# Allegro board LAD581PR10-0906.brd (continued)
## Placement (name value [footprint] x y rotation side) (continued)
PC720  100P_0402_50V8J  [C_0402]  60.01 39.45 270 top
PC721  0.1U_0402_25V6  [C_0402]  52.02 35.38 90 top
PC722  1000P_0402_50V7K  [C_0402]  47.37 50 0 bottom
PC723  1000P_0402_50V7K  [C_0402]  47.39 43.07 180 top
PC724  0.1U_0402_25V6  [C_0402]  89.13 72.17 180 top
PC725  0.022U_0603_25V7K  [C_0603]  65.04 22.95 180 top
PC726  1000P_0402_50V7K  [C_0402]  55.57 28.67 90 top
PC727  1U_0402_25V6K  [C_0402]  56.46 28.67 90 top
PC800  10U_0805_25V6K~D  [C_0805]  162.36 149.69 0 bottom
PC801  0.01U_0402_16V7K  [C_0402]  161.76 155.79 180 bottom
PC802  680P_0402_50V7K  [C_0402]  162.26 150 90 top
PC803  2.2U_0402_16V6K  [C_0402]  168.4 155.28 0 bottom
PC804  22U_0603_6.3V6M  [C_0603]  173.56 153.12 90 bottom
PC805  22U_0603_6.3V6M  [C_0603]  174.83 153.12 90 bottom
PC806  680P_0402_50V7K  [C_0402]  238.77 148.37 270 bottom
PC807  2.2U_0402_16V6K  [C_0402]  93.74 103.8 270 bottom
PC808  0.1U_0603_25V7K  [C_0603]  166.57 148.7 90 bottom
PC809  330P_0402_50V7K  [C_0402]  165.43 158.41 270 bottom
PC810  10U_0603_6.3V6M  [C_0603]  240.55 148.23 0 bottom
PC811  0.1U_0402_16V7K  [C_0402]  238.9 154.06 90 bottom
PC812  22U_0603_6.3V6M  [C_0603]  234.91 148.05 180 bottom
PC813  22U_0603_6.3V6M  [C_0603]  234.91 149.31 180 bottom
PC814  1U_0603_6.3V6M  [C_0603]  240.55 149.5 0 bottom
PC815  22U_0603_6.3V6M  [C_0603]  235.89 148.05 0 bottom
PC816  22P_0603_50V8  [C_0603]  243.03 154.71 270 bottom
PC817  1U_0603_6.3V6M  [C_0603]  166.64 156.55 0 bottom
PC818  22U_0603_6.3V6M  [C_0603]  168.23 153.57 90 top
PC819  22U_0603_6.3V6M  [C_0603]  169.42 153.57 90 top
PC820  330P_0402_50V7K  [C_0402]  92.55 113.82 180 bottom
PC1000  220U_D7_2VM_R6M  [C_EEFSS0D221R]  134.04 117.65 0 bottom
PC1001  220U 2.5V Y D2 ESR9M H1.9 SX  [C_D2]  131.47 119.64 0 top
PC1002  220U 2.5V Y D2 ESR9M H1.9 SX  [C_D2]  141.65 119.63 0 top
PC1003  47U_0805_6.3V6M  [C_0805]  148.54 118.18 270 bottom
PC1004  47U_0805_6.3V6M  [C_0805]  146.63 118.18 270 bottom
PC1005  47U_0805_6.3V6M  [C_0805]  135.25 98.59 0 top
PC1006  47U_0805_6.3V6M  [C_0805]  150.44 118.18 270 bottom
PC1007  220U 2.5V Y D2 ESR9M H1.9 SX  [C_D2]  120.45 119.59 0 top
PC1008  220U_D7_2VM_R6M  [C_EEFSS0D221R]  120.25 117.69 180 bottom
PC1009  220U_D7_2VM_R6M  [C_EEFSS0D221R]  110.02 117.33 180 bottom
PC1010  220U_D7_2VM_R6M  [C_EEFSS0D221R]  124.32 117.75 0 bottom
PC1011  47U_0805_6.3V6M  [C_0805]  110.25 120.48 90 top
PC1012  47U_0805_6.3V6M  [C_0805]  117.36 120.48 90 top
PC1013  47U_0805_6.3V6M  [C_0805]  112.03 120.48 90 top
PC1014  47U_0805_6.3V6M  [C_0805]  120.56 122.96 180 top
PC1015  47U_0805_6.3V6M  [C_0805]  113.8 120.48 90 top
PC1016  47U_0805_6.3V6M  [C_0805]  115.58 120.48 90 top
PC1017  220U_D2_2.5VY_R9M  [C_D2]  151.75 119.53 0 top
PC1018  47U_0805_6.3V6M  [C_0805]  135.25 100.3 0 top
PC1019  10U_0402_6.3V6M  [C_0402]  136.03 104.56 0 top
PC1020  22U_0603_6.3V6M  [C_0603]  127.34 99.16 0 top
PC1021  22U_0603_6.3V6M  [C_0603]  127.34 97.96 0 top
PC1022  22U_0603_6.3V6M  [C_0603]  126.39 99.16 180 top
PC1023  22U_0603_6.3V6M  [C_0603]  126.39 97.96 180 top
PC1024  22U_0603_6.3V6M  [C_0603]  131.09 97.96 180 top
PC1025  22U_0603_6.3V6M  [C_0603]  131.09 99.16 180 top
PC1026  22U_0603_6.3V6M  [C_0603]  132.04 99.16 0 top
PC1027  22U_0603_6.3V6M  [C_0603]  132.04 97.96 0 top
PC1028  22U_0603_6.3V6M  [C_0603]  111.21 99.54 0 top
PC1029  22U_0603_6.3V6M  [C_0603]  108.86 99.54 0 top
PC1030  22U_0603_6.3V6M  [C_0603]  115.91 99.54 0 top
PC1031  22U_0603_6.3V6M  [C_0603]  113.56 99.54 0 top
PC1032  22U_0603_6.3V6M  [C_0603]  118.26 99.54 0 top
PC1033  22U_0603_6.3V6M  [C_0603]  120.99 99.61 0 top
PC1034  22U_0603_6.3V6M  [C_0603]  121 100.82 0 top
PC1035  22U_0603_6.3V6M  [C_0603]  121 102.16 0 top
PC1036  10U_0402_6.3V6M  [C_0402]  135.16 102.53 180 top
PC1037  10U_0402_6.3V6M  [C_0402]  136.03 103.67 0 top
PC1038  10U_0402_6.3V6M  [C_0402]  136.03 105.96 0 top
PC1039  10U_0402_6.3V6M  [C_0402]  135.16 103.42 180 top
PC1040  10U_0402_6.3V6M  [C_0402]  135.16 101.64 180 top
PC1041  10U_0402_6.3V6M  [C_0402]  136.03 101.64 0 top
PC1042  1U_0201_6.3V6M  [C_0201]  135.32 105.19 180 top
PC1043  1U_0201_6.3V6M  [C_0201]  135.32 106.34 180 top
PC1044  1U_0201_6.3V6M  [C_0201]  135.32 105.77 180 top
PC1045  10U_0402_6.3V6M  [C_0402]  125.96 102.53 180 top
PC1046  10U_0402_6.3V6M  [C_0402]  126.82 101.26 0 top
PC1047  10U_0402_6.3V6M  [C_0402]  125.96 103.42 180 top
PC1048  10U_0402_6.3V6M  [C_0402]  125.96 101.26 180 top
PC1049  10U_0402_6.3V6M  [C_0402]  126.82 103.42 0 top
PC1050  10U_0402_6.3V6M  [C_0402]  129.39 96.69 180 top
PC1051  10U_0402_6.3V6M  [C_0402]  126.82 102.53 0 top
PC1052  10U_0402_6.3V6M  [C_0402]  126.69 96.69 0 top
PC1053  10U_0402_6.3V6M  [C_0402]  129.39 95.8 180 top
PC1054  10U_0402_6.3V6M  [C_0402]  130.57 101.26 0 top
PC1055  10U_0402_6.3V6M  [C_0402]  126.69 95.8 0 top
PC1056  10U_0402_6.3V6M  [C_0402]  129.7 101.26 180 top
PC1057  10U_0402_6.3V6M  [C_0402]  129.7 103.42 180 top
PC1058  10U_0402_6.3V6M  [C_0402]  129.7 102.53 180 top
PC1059  10U_0402_6.3V6M  [C_0402]  123.56 104.22 180 top
PC1060  10U_0402_6.3V6M  [C_0402]  113.6 97.22 0 top
PC1061  10U_0402_6.3V6M  [C_0402]  109.04 96.3 0 top
PC1062  10U_0402_6.3V6M  [C_0402]  111.32 98.1 0 top
PC1063  10U_0402_6.3V6M  [C_0402]  111.33 102.89 0 top
PC1064  10U_0402_6.3V6M  [C_0402]  118.51 100.62 0 top
PC1065  10U_0402_6.3V6M  [C_0402]  116.04 100.61 0 top
PC1066  10U_0402_6.3V6M  [C_0402]  109.08 101.98 0 top
PC1067  10U_0402_6.3V6M  [C_0402]  113.62 102.89 0 top
PC1068  10U_0402_6.3V6M  [C_0402]  109.04 97.2 0 top
PC1069  10U_0402_6.3V6M  [C_0402]  113.6 96.31 0 top
PC1070  10U_0402_6.3V6M  [C_0402]  111.34 102.02 0 top
PC1071  10U_0402_6.3V6M  [C_0402]  130.57 103.42 0 top
PC1072  10U_0402_6.3V6M  [C_0402]  130.25 95.8 0 top
PC1073  10U_0402_6.3V6M  [C_0402]  130.57 102.53 0 top
PC1074  10U_0402_6.3V6M  [C_0402]  130.25 96.69 0 top
PC1075  10U_0402_6.3V6M  [C_0402]  133.26 103.42 180 top
PC1076  10U_0402_6.3V6M  [C_0402]  133.26 101.26 180 top
PC1077  10U_0402_6.3V6M  [C_0402]  132.94 95.8 180 top
PC1078  10U_0402_6.3V6M  [C_0402]  133.26 102.53 180 top
PC1079  10U_0402_6.3V6M  [C_0402]  133.81 95.8 0 top
PC1080  10U_0402_6.3V6M  [C_0402]  133.81 96.69 0 top
PC1081  10U_0402_6.3V6M  [C_0402]  136.5 96.69 180 top
PC1082  10U_0402_6.3V6M  [C_0402]  132.94 96.69 180 top
PC1083  10U_0402_6.3V6M  [C_0402]  125.83 96.69 180 top
PC1084  10U_0402_6.3V6M  [C_0402]  125.83 95.8 180 top
PC1085  10U_0402_6.3V6M  [C_0402]  118.26 96.29 0 top
PC1086  10U_0402_6.3V6M  [C_0402]  118.27 98.09 0 top
PC1087  10U_0402_6.3V6M  [C_0402]  115.93 96.29 0 top
PC1088  10U_0402_6.3V6M  [C_0402]  118.45 102.94 0 top
PC1089  10U_0402_6.3V6M  [C_0402]  115.92 98.09 0 top
PC1090  10U_0402_6.3V6M  [C_0402]  120.53 96.3 0 top
PC1091  10U_0402_6.3V6M  [C_0402]  123.53 103.35 180 top
PC1092  10U_0402_6.3V6M  [C_0402]  115.92 97.19 0 top
PC1093  10U_0402_6.3V6M  [C_0402]  120.54 97.18 0 top
PC1094  10U_0402_6.3V6M  [C_0402]  111.31 96.31 0 top
PC1095  10U_0402_6.3V6M  [C_0402]  115.97 102.9 0 top
PC1096  10U_0402_6.3V6M  [C_0402]  113.62 102.02 0 top
PC1097  1U_0201_6.3V6M  [C_0201]  133.6 92.62 180 top
PC1098  1U_0201_6.3V6M  [C_0201]  135.13 94.08 180 top
PC1099  1U_0201_6.3V6M  [C_0201]  128.93 107.92 315 top
PC1100  1U_0201_6.3V6M  [C_0201]  130.3 100.5 180 top
PC1101  1U_0201_6.3V6M  [C_0201]  135.75 94.08 0 top
PC1102  1U_0201_6.3V6M  [C_0201]  133.08 104.75 0 top
PC1103  1U_0201_6.3V6M  [C_0201]  133.08 104.18 0 top
PC1104  1U_0201_6.3V6M  [C_0201]  132.46 104.75 180 top
PC1105  1U_0201_6.3V6M  [C_0201]  132.71 100.5 180 top
PC1106  1U_0201_6.3V6M  [C_0201]  132.46 104.18 180 top
PC1107  1U_0201_6.3V6M  [C_0201]  132.46 105.77 180 top
PC1108  1U_0201_6.3V6M  [C_0201]  132.46 106.34 180 top
PC1109  1U_0201_6.3V6M  [C_0201]  133.08 106.34 0 top
PC1110  1U_0201_6.3V6M  [C_0201]  133.08 105.77 0 top
PC1111  1U_0201_6.3V6M  [C_0201]  130.92 100.5 0 top
PC1112  10U_0402_6.3V6M  [C_0402]  115.99 102.02 0 top
PC1113  10U_0402_6.3V6M  [C_0402]  120.56 98.08 0 top
PC1114  10U_0402_6.3V6M  [C_0402]  109.04 98.1 0 top
PC1115  10U_0402_6.3V6M  [C_0402]  111.36 100.62 0 top
PC1116  10U_0402_6.3V6M  [C_0402]  111.32 97.2 0 top
PC1117  10U_0402_6.3V6M  [C_0402]  109.08 102.87 0 top
PC1118  10U_0402_6.3V6M  [C_0402]  109.06 100.63 0 top
PC1119  10U_0402_6.3V6M  [C_0402]  118.46 102.03 0 top
PC1120  10U_0402_6.3V6M  [C_0402]  113.6 98.12 0 top
PC1121  10U_0402_6.3V6M  [C_0402]  118.27 97.19 0 top
PC1122  10U_0402_6.3V6M  [C_0402]  113.6 100.61 0 top
PC1123  1U_0201_6.3V6M  [C_0201]  125.84 104.75 0 top
PC1124  1U_0201_6.3V6M  [C_0201]  127.63 104.18 180 top
PC1125  1U_0201_6.3V6M  [C_0201]  125.84 104.18 0 top
PC1126  1U_0201_6.3V6M  [C_0201]  125.22 104.75 180 top
PC1127  1U_0201_6.3V6M  [C_0201]  127.63 104.75 180 top
PC1128  1U_0201_6.3V6M  [C_0201]  127.63 106.34 180 top
PC1129  1U_0201_6.3V6M  [C_0201]  125.22 104.18 180 top
PC1130  1U_0201_6.3V6M  [C_0201]  127.63 105.77 180 top
PC1131  1U_0201_6.3V6M  [C_0201]  125.84 106.34 0 top
PC1132  1U_0201_6.3V6M  [C_0201]  125.84 105.77 0 top
PC1133  1U_0201_6.3V6M  [C_0201]  125.22 105.77 180 top
PC1134  1U_0201_6.3V6M  [C_0201]  134.22 92.62 0 top
PC1135  1U_0201_6.3V6M  [C_0201]  125.22 106.34 180 top
PC1136  1U_0201_6.3V6M  [C_0201]  133.34 100.5 0 top
PC1137  1U_0201_6.3V6M  [C_0201]  130.92 94.65 0 top
PC1138  1U_0201_6.3V6M  [C_0201]  123.05 105.4 180 top
PC1139  1U_0201_6.3V6M  [C_0201]  116.35 105.94 0 top
PC1140  1U_0201_6.3V6M  [C_0201]  114.51 95 180 top
PC1141  1U_0201_6.3V6M  [C_0201]  120.61 105.39 180 top
PC1142  1U_0201_6.3V6M  [C_0201]  120.66 103.76 180 top
PC1143  1U_0201_6.3V6M  [C_0201]  117.16 95.01 180 top
PC1144  1U_0201_6.3V6M  [C_0201]  119.57 94.44 180 top
PC1145  1U_0201_6.3V6M  [C_0201]  108.97 104.28 0 top
PC1146  1U_0201_6.3V6M  [C_0201]  119.57 95.01 180 top
PC1147  1U_0201_6.3V6M  [C_0201]  114.51 94.42 180 top
PC1148  1U_0201_6.3V6M  [C_0201]  120.19 94.44 0 top
PC1149  1U_0201_6.3V6M  [C_0201]  110.79 103.69 180 top
PC1150  1U_0201_6.3V6M  [C_0201]  120.66 104.35 180 top
PC1151  1U_0201_6.3V6M  [C_0201]  111.44 104.28 0 top
PC1152  1U_0201_6.3V6M  [C_0201]  118.86 103.76 0 top
PC1153  1U_0201_6.3V6M  [C_0201]  113.27 103.69 180 top
PC1154  1U_0201_6.3V6M  [C_0201]  118.86 104.34 0 top
PC1155  1U_0201_6.3V6M  [C_0201]  113.93 104.29 0 top
PC1156  1U_0201_6.3V6M  [C_0201]  120.19 95.01 0 top
PC1157  1U_0201_6.3V6M  [C_0201]  118.81 105.38 0 top
PC1158  1U_0201_6.3V6M  [C_0201]  121.29 103.78 0 top
PC1159  1U_0201_6.3V6M  [C_0201]  118.81 105.96 0 top
PC1160  1U_0201_6.3V6M  [C_0201]  123.05 105.97 180 top
PC1161  1U_0201_6.3V6M  [C_0201]  127.78 107.5 135 top
PC1162  1U_0201_6.3V6M  [C_0201]  132.5 107.5 135 top
PC1163  1U_0201_6.3V6M  [C_0201]  132.71 94.65 180 top
PC1164  1U_0201_6.3V6M  [C_0201]  133.34 94.65 0 top
PC1165  1U_0201_6.3V6M  [C_0201]  128.51 94.65 0 top
PC1166  1U_0201_6.3V6M  [C_0201]  128.51 100.5 0 top
PC1167  1U_0201_6.3V6M  [C_0201]  130.3 94.65 180 top
PC1168  1U_0201_6.3V6M  [C_0201]  130.05 104.18 180 top
PC1169  1U_0201_6.3V6M  [C_0201]  127.89 100.5 180 top
PC1170  1U_0201_6.3V6M  [C_0201]  130.67 104.75 0 top
PC1171  1U_0201_6.3V6M  [C_0201]  130.05 104.75 180 top
PC1172  1U_0201_6.3V6M  [C_0201]  130.67 104.18 0 top
PC1173  1U_0201_6.3V6M  [C_0201]  128.26 104.18 0 top
PC1174  1U_0201_6.3V6M  [C_0201]  128.26 104.75 0 top
PC1175  1U_0201_6.3V6M  [C_0201]  130.05 105.77 180 top
PC1176  1U_0201_6.3V6M  [C_0201]  115.36 95.01 0 top
PC1177  1U_0201_6.3V6M  [C_0201]  116.38 103.73 0 top
PC1178  1U_0201_6.3V6M  [C_0201]  115.36 94.44 0 top
PC1179  1U_0201_6.3V6M  [C_0201]  116.35 105.36 0 top
PC1180  1U_0201_6.3V6M  [C_0201]  113.25 105.34 180 top
PC1181  1U_0201_6.3V6M  [C_0201]  117.78 95.01 0 top
PC1182  1U_0201_6.3V6M  [C_0201]  117.16 94.44 180 top
PC1183  1U_0201_6.3V6M  [C_0201]  115.71 105.93 180 top
PC1184  1U_0201_6.3V6M  [C_0201]  115.75 104.3 180 top
PC1185  1U_0201_6.3V6M  [C_0201]  115.71 105.35 180 top
PC1186  1U_0201_6.3V6M  [C_0201]  110.3 94.42 0 top
PC1187  1U_0201_6.3V6M  [C_0201]  108.96 103.69 0 top
PC1188  1U_0201_6.3V6M  [C_0201]  110.79 104.27 180 top
PC1189  1U_0201_6.3V6M  [C_0201]  109.68 94.99 180 top
PC1190  1U_0201_6.3V6M  [C_0201]  110.78 105.92 180 top
PC1191  1U_0201_6.3V6M  [C_0201]  109.68 94.42 180 top
PC1192  1U_0201_6.3V6M  [C_0201]  110.78 105.34 180 top
PC1193  1U_0201_6.3V6M  [C_0201]  115.75 103.71 180 top
PC1194  1U_0201_6.3V6M  [C_0201]  120.61 105.97 180 top
PC1195  1U_0201_6.3V6M  [C_0201]  113.9 105.36 0 top
PC1196  1U_0201_6.3V6M  [C_0201]  111.44 103.69 0 top
PC1197  1U_0201_6.3V6M  [C_0201]  113.89 105.93 0 top
PC1198  1U_0201_6.3V6M  [C_0201]  117.78 94.44 0 top
PC1199  1U_0201_6.3V6M  [C_0201]  130.05 106.34 180 top
PC1200  1U_0201_6.3V6M  [C_0201]  128.26 105.77 0 top
PC1201  1U_0201_6.3V6M  [C_0201]  128.26 106.34 0 top
PC1202  1U_0201_6.3V6M  [C_0201]  130.67 105.77 0 top
PC1203  1U_0201_6.3V6M  [C_0201]  130.67 106.34 0 top
PC1204  1U_0201_6.3V6M  [C_0201]  135.75 94.65 0 top
PC1205  1U_0201_6.3V6M  [C_0201]  135.13 94.65 180 top
PC1206  1U_0201_6.3V6M  [C_0201]  125.47 94.08 180 top
PC1207  1U_0201_6.3V6M  [C_0201]  130.93 107.5 135 top
PC1208  1U_0201_6.3V6M  [C_0201]  125.47 94.65 180 top
PC1209  1U_0201_6.3V6M  [C_0201]  126.1 94.65 0 top
PC1210  1U_0201_6.3V6M  [C_0201]  125.92 93.26 180 top
PC1211  1U_0201_6.3V6M  [C_0201]  126.1 94.08 0 top
PC1212  1U_0201_6.3V6M  [C_0201]  127.89 94.08 180 top
PC1213  1U_0201_6.3V6M  [C_0201]  128.33 92.62 180 top
PC1214  1U_0201_6.3V6M  [C_0201]  116.38 104.31 0 top
PC1215  1U_0201_6.3V6M  [C_0201]  113.27 104.28 180 top
PC1216  1U_0201_6.3V6M  [C_0201]  121.29 104.37 0 top
PC1217  1U_0201_6.3V6M  [C_0201]  118.17 105.95 180 top
PC1218  1U_0201_6.3V6M  [C_0201]  121.25 105.39 0 top
PC1219  1U_0201_6.3V6M  [C_0201]  111.43 105.91 0 top
PC1220  1U_0201_6.3V6M  [C_0201]  121.98 94.44 180 top
PC1221  1U_0201_6.3V6M  [C_0201]  113.92 103.7 0 top
PC1222  1U_0201_6.3V6M  [C_0201]  113.25 105.92 180 top
PC1223  1U_0201_6.3V6M  [C_0201]  112.72 94.99 0 top
PC1224  1U_0201_6.3V6M  [C_0201]  111.43 105.32 0 top
PC1225  1U_0201_6.3V6M  [C_0201]  108.96 105.34 0 top
PC1226  1U_0201_6.3V6M  [C_0201]  108.95 105.93 0 top
PC1227  1U_0201_6.3V6M  [C_0201]  110.3 94.99 0 top
PC1228  1U_0201_6.3V6M  [C_0201]  121.25 105.96 0 top
PC1229  1U_0201_6.3V6M  [C_0201]  112.1 94.43 180 top
PC1230  1U_0201_6.3V6M  [C_0201]  118.22 103.75 180 top
PC1231  1U_0201_6.3V6M  [C_0201]  112.73 94.41 0 top
PC1232  1U_0201_6.3V6M  [C_0201]  118.17 105.36 180 top
PC1233  1U_0201_6.3V6M  [C_0201]  121.98 95.01 180 top
PC1234  1U_0201_6.3V6M  [C_0201]  118.22 104.33 180 top
PC1235  1U_0201_6.3V6M  [C_0201]  112.1 95 180 top
PC1236  1U_0201_6.3V6M  [C_0201]  126.1 100.5 0 top
PC1237  1U_0201_6.3V6M  [C_0201]  127.89 94.65 180 top
PC1238  1U_0201_6.3V6M  [C_0201]  125.47 100.5 180 top
PC1300  22U_0603_6.3V6M  [C_0603]  163.87 17.33 180 bottom
PC1301  0.1U_0402_16V7K  [C_0402]  164.9 19.56 270 bottom
PC1303  22U_0603_6.3V6M  [C_0603]  160.35 26.82 180 bottom
PC1304  22U_0603_6.3V6M  [C_0603]  160.35 25.55 180 bottom
PC1305  22P_0603_50V8  [C_0603]  163.46 28.03 0 bottom
PC1306  22U_0603_6.3V6M  [C_0603]  163.87 18.53 180 bottom
PC1307  1U_0603_6.3V6M  [C_0603]  160.03 20.34 180 bottom
PC5002  4.7U_0402_6.3V6M  [C_0402]  153.3 126.44 90 top
PC5003  1U_0603_6.3V6M  [C_0603]  95.07 104.88 270 bottom
PC5005  1U_0402_6.3V6K  [C_0402]  129.01 132.18 270 top
PC5006  1U_0402_6.3V6K  [C_0402]  137.52 132.18 270 top
PC5007  1U_0402_6.3V6K  [C_0402]  145.52 132.22 270 top
PC5008  1U_0402_6.3V6K  [C_0402]  112.57 132.17 270 top
PC5009  1U_0402_6.3V6K  [C_0402]  120.87 132.28 270 top
PC5010  1000P_0402_50V7K  [C_0402]  86.61 126.47 0 bottom
PC5011  1000P_0402_50V7K  [C_0402]  87.55 139.32 270 bottom
PC5012  33U_D2_25VM_R40M  [C_EEFCX1E330R]  102.35 122.03 180 bottom
PC5013  1U_0402_25V6K  [C_0402]  135.98 135.35 90 top
PC5014  1000P_0402_50V7K  [C_0402]  135.12 135.35 90 top
PC5015  1U_0402_25V6K  [C_0402]  143.55 135.35 90 top
PC5016  1000P_0402_50V7K  [C_0402]  144.41 135.35 90 top
PC5017  1U_0402_25V6K  [C_0402]  152.09 135.48 90 top
PC5018  1000P_0402_50V7K  [C_0402]  152.98 135.48 90 top
PC5019  1U_0402_25V6K  [C_0402]  119.52 135.29 90 top
PC5020  1000P_0402_50V7K  [C_0402]  118.66 135.29 90 top
PC5021  1U_0402_25V6K  [C_0402]  127.65 135.35 90 top
PC5022  1000P_0402_50V7K  [C_0402]  126.78 135.35 90 top
PC5023  1U_0402_25V6K  [C_0402]  156.62 127.76 180 top
PC5024  1000P_0402_50V7K  [C_0402]  156.62 128.62 180 top
PC5025  1U_0402_25V6K  [C_0402]  88.09 108.81 90 top
PC5026  1000P_0402_50V7K  [C_0402]  88.98 108.81 90 top
PC6100  4.7U_0603_6.3V  [C_0603]  200.1 34.25 270 top
PC6101  1U_0402_25V6K  [C_0402]  208.06 42.95 180 top
PC6102  1000P_0402_50V7K  [C_0402]  208 39.46 180 top
PC6103  0.1U_0402_25V6  [C_0402]  208.06 42.08 180 top
PC6104  2200P_0402_50V7K  [C_0402]  208 40.33 180 top
PC6105  10U_0805_25V6K~D  [C_0805]  208.23 44.92 180 top
PC6106  10U_0805_25V6K~D  [C_0805]  208.23 46.64 180 top
PC6107  0.22U_0603_25V7K  [C_0603]  202.17 34.85 0 bottom
PC6108  0.22U_0603_25V7K  [C_0603]  198.55 34.74 180 bottom
PC6109  10P_0402_25V8J  [C_0402]  196.42 30.36 90 top
PC6110  330P_0402_50V8J  [C_0402]  195.27 31.81 90 top
PC6111  1U_0402_25V6K  [C_0402]  193.98 39.95 0 top
PC6112  1000P_0402_50V7K  [C_0402]  193.92 42.68 0 top
PC6113  0.1U_0402_25V6  [C_0402]  193.98 40.82 0 top
PC6114  2200P_0402_50V7K  [C_0402]  193.92 43.59 0 top
PC6115  10U_0805_25V6K~D  [C_0805]  193.82 47.18 0 top
PC6116  10U_0805_25V6K~D  [C_0805]  193.82 45.45 0 top
PC6117  47P_0402_50V8J  [C_0402]  196.38 28.61 180 bottom
PC6118  4700P_0402_50V7K  [C_0402]  199.42 27.84 180 top
PC6119  1000P_0402_25V  [C_0402]  197.5 27.65 270 bottom
PC6120  0.01U_0402_16V  [C_0402]  198.5 28.79 0 top
PC6121  1500P_0402_50V7K  [C_0402]  202.88 27.64 270 bottom
PC6122  33U_D2_25VM_R40M  [C_EEFCX1E330R]  234.65 49.72 270 bottom
PC6123  33U_D2_25VM_R40M  [C_EEFCX1E330R]  229.71 49.73 270 bottom
PC6124  33U_D2_25VM_R40M  [C_EEFCX1E330R]  239.48 49.71 270 bottom
PC6125  2200P_0603_50V7K  [C_0603]  202.07 36.03 0 top
PC6126  2200P_0603_50V7K  [C_0603]  200.99 36.03 180 top
PC6129  470U_D2_2VM_R4.5M~D  [C_D1]  199.94 61.31 270 top
PC6130  10U_0805_25V6K~D  [C_0805]  207.76 34.26 90 bottom
PC6131  10U_0805_25V6K~D  [C_0805]  209.59 34.24 90 bottom
PC6132  10U_0805_25V6K~D  [C_0805]  212.78 35.11 180 bottom
PC6133  10U_0805_25V6K~D  [C_0805]  189.19 47.22 0 bottom
PC6134  10U_0805_25V6K~D  [C_0805]  189.18 45.45 0 bottom
PC6135  10U_0805_25V6K~D  [C_0805]  189.17 43.71 0 bottom
PC6200  4.7U_0603_6.3V  [C_0603]  212.74 34.12 270 top
PC6201  1U_0402_25V6K  [C_0402]  217.78 43.49 180 top
PC6202  1000P_0402_50V7K  [C_0402]  217.78 42.6 180 top
PC6203  0.1U_0402_25V6  [C_0402]  217.78 39.82 180 top
PC6204  2200P_0402_50V7K  [C_0402]  217.78 40.74 180 top
PC6205  10U_0805_25V6K~D  [C_0805]  217.95 47.13 180 top
PC6206  10U_0805_25V6K~D  [C_0805]  217.95 45.36 180 top
PC6207  0.22U_0603_25V7K  [C_0603]  214.34 34.77 0 bottom
PC6209  10P_0402_25V8J  [C_0402]  209.05 31.26 90 top
PC6210  330P_0402_50V8J  [C_0402]  207.97 32.13 90 top
PC6211  47P_0402_50V8J  [C_0402]  209.59 29.31 180 bottom
PC6212  4700P_0402_50V7K  [C_0402]  212.75 27.84 180 top
PC6213  1000P_0402_25V  [C_0402]  210.33 27.85 270 bottom
PC6214  0.01U_0402_16V  [C_0402]  211.84 29.42 0 top
PC6215  1500P_0402_50V7K  [C_0402]  215.71 27.83 270 bottom
PC6217  33U_D2_25VM_R40M  [C_EEFCX1E330R]  224.87 49.72 270 bottom
PC6218  2200P_0603_50V7K  [C_0603]  217.95 36.73 270 top
PC6219  10U_0805_25V6K~D  [C_0805]  217.07 34.43 90 bottom
PC6220  10U_0805_25V6K~D  [C_0805]  221.21 49.76 270 bottom
PC6221  10U_0805_25V6K~D  [C_0805]  218.78 34.44 90 bottom
PC6300  1U_0402_6.3V6K  [C_0402]  199.71 106.51 0 top
PC6301  1U_0402_6.3V6K  [C_0402]  198.72 103.08 0 top
PC6302  1U_0402_6.3V6K  [C_0402]  205.2 68.48 180 bottom
PC6303  1U_0402_6.3V6K  [C_0402]  190.21 88.35 180 top
PC6304  1U_0402_6.3V6K  [C_0402]  197.68 68.48 0 bottom
PC6305  1U_0402_6.3V6K  [C_0402]  189.49 91.91 0 top
PC6306  1U_0402_6.3V6K  [C_0402]  191.28 91.91 0 top
PC6307  1U_0402_6.3V6K  [C_0402]  193.96 91.91 180 top
PC6308  1U_0402_6.3V6K  [C_0402]  188.62 93.31 180 top
PC6309  1U_0402_6.3V6K  [C_0402]  188.62 94.7 180 top
PC6310  1U_0402_6.3V6K  [C_0402]  189.49 93.31 0 top
PC6311  1U_0402_6.3V6K  [C_0402]  189.49 94.7 0 top
PC6312  1U_0402_6.3V6K  [C_0402]  200.47 100.29 0 top
PC6313  1U_0402_6.3V6K  [C_0402]  198.72 100.29 0 top
PC6314  1U_0402_6.3V6K  [C_0402]  203.86 104.48 180 top
PC6315  1U_0402_6.3V6K  [C_0402]  198.26 104.48 0 top
PC6316  1U_0402_6.3V6K  [C_0402]  193.88 105.18 0 top
PC6317  1U_0402_6.3V6K  [C_0402]  189 105.31 270 top
PC6318  1U_0402_6.3V6K  [C_0402]  188.61 90.51 180 top
PC6319  1U_0402_6.3V6K  [C_0402]  195.61 90.51 180 top
PC6320  1U_0402_6.3V6K  [C_0402]  196.47 89.88 0 top
PC6321  1U_0402_6.3V6K  [C_0402]  190.83 105.18 180 top
PC6322  1U_0402_6.3V6K  [C_0402]  202.25 101.62 0 top
PC6323  1U_0402_6.3V6K  [C_0402]  205.2 69.39 180 bottom
PC6324  1U_0402_6.3V6K  [C_0402]  200.42 69.43 180 bottom
PC6325  1U_0402_6.3V6K  [C_0402]  196.97 101.62 0 top
PC6326  1U_0402_6.3V6K  [C_0402]  196.97 100.29 0 top
PC6327  1U_0402_6.3V6K  [C_0402]  182.45 112.91 90 top
PC6328  1U_0402_6.3V6K  [C_0402]  197.68 70.32 0 bottom
PC6329  1U_0402_6.3V6K  [C_0402]  200.43 68.48 180 bottom
PC6330  1U_0402_6.3V6K  [C_0402]  188.62 91.91 180 top
PC6331  1U_0402_6.3V6K  [C_0402]  196.5 88.42 180 top
PC6332  1U_0402_6.3V6K  [C_0402]  181.43 112.91 90 top
PC6333  1U_0402_6.3V6K  [C_0402]  198.72 101.62 0 top
PC6334  1U_0402_6.3V6K  [C_0402]  202.26 100.29 0 top
PC6335  1U_0402_6.3V6K  [C_0402]  187.72 109.87 90 top
PC6336  1U_0402_6.3V6K  [C_0402]  193.82 90.51 180 top
PC6337  1U_0402_6.3V6K  [C_0402]  200.93 104.48 0 top
PC6338  1U_0402_6.3V6K  [C_0402]  196.41 104.48 0 top
PC6339  1U_0402_6.3V6K  [C_0402]  191.64 105.18 0 top
PC6340  1U_0402_6.3V6K  [C_0402]  190.9 90.51 0 top
PC6341  1U_0402_6.3V6K  [C_0402]  201.13 89.88 180 top
PC6342  1U_0402_6.3V6K  [C_0402]  203.93 90.45 180 top
PC6343  1U_0402_6.3V6K  [C_0402]  198.25 89.88 0 top
PC6344  1U_0402_6.3V6K  [C_0402]  183.47 112.91 90 top
PC6345  1U_0402_6.3V6K  [C_0402]  199.53 88.48 0 top
PC6346  1U_0402_6.3V6K  [C_0402]  202.25 103.02 0 top
PC6347  1U_0402_6.3V6K  [C_0402]  189.24 106.58 0 top
PC6348  1U_0402_6.3V6K  [C_0402]  193.96 93.31 180 top
PC6349  1U_0402_6.3V6K  [C_0402]  191.28 93.31 0 top
PC6350  1U_0402_6.3V6K  [C_0402]  206.01 93.95 270 top
PC6351  1U_0402_6.3V6K  [C_0402]  193.96 94.7 180 top
PC6352  1U_0402_6.3V6K  [C_0402]  205.18 70.28 180 bottom
PC6353  1U_0402_6.3V6K  [C_0402]  202.2 88.48 180 top
PC6354  1U_0402_6.3V6K  [C_0402]  197.68 69.43 0 bottom
PC6355  1U_0402_6.3V6K  [C_0402]  188.61 108.03 90 top
PC6356  1U_0402_6.3V6K  [C_0402]  191.28 94.7 0 top
PC6357  1U_0402_6.3V6K  [C_0402]  186.5 109.93 90 top
PC6358  1U_0402_6.3V6K  [C_0402]  206.02 100.29 180 top
PC6359  22U_0805_6.3VAM  [C_0805]  178.32 111.11 270 top
PC6360  47U_0805_6.3V6M  [C_0805]  180.23 111.49 270 top
PC6361  22U_0805_10V6M  [C_0805]  227.6 61.9 270 top
PC6362  22U_0805_10V6M  [C_0805]  229.38 61.9 270 top
PC6363  470U_D2_2VM_R4.5M~D  [C_D1]  218.61 65.14 90 bottom
PC6364  1U_0402_6.3V6K  [C_0402]  200.47 101.62 0 top
PC6365  1U_0402_6.3V6K  [C_0402]  206.02 101.62 180 top
PC6366  1U_0402_6.3V6K  [C_0402]  177.05 112.79 90 top
PC6367  1U_0402_6.3V6K  [C_0402]  196.97 103.08 0 top
PC6368  1U_0402_6.3V6K  [C_0402]  200.47 103.02 0 top
PC6369  1U_0402_6.3V6K  [C_0402]  176.93 111.29 270 top
PC6370  22U_0805_6.3VAM  [C_0805]  182.45 109.97 270 top
PC6371  22U_0805_6.3VAM  [C_0805]  184.55 107.94 270 top
PC6372  22U_0805_6.3VAM  [C_0805]  185.22 110.23 90 top
PC6373  47U_0805_6.3V6M  [C_0805]  186.64 106.03 270 top
PC6374  22U_0805_10V6M  [C_0805]  217.63 62.03 270 top
PC6375  22U_0805_10V6M  [C_0805]  214.07 62.03 270 top
PC6376  22U_0805_10V6M  [C_0805]  225.88 61.9 270 top
PC6377  22U_0805_10V6M  [C_0805]  224.11 61.9 270 top
PC6378  22U_0805_10V6M  [C_0805]  215.85 62.03 270 top
PC6379  4.7U_0603_6.3V6K  [C_0603]  193.37 61.87 270 top
PC6380  4.7U_0603_6.3V6K  [C_0603]  207.72 61.87 270 top
PC6381  4.7U_0603_6.3V6K  [C_0603]  189.69 61.75 0 top
PC6382  4.7U_0603_6.3V6K  [C_0603]  212.55 61.87 270 top
PC6383  4.7U_0603_6.3V6K  [C_0603]  192.17 61.87 270 top
PC6384  4.7U_0603_6.3V6K  [C_0603]  189.63 55.65 0 top
PC6385  4.7U_0603_6.3V6K  [C_0603]  194.57 61.87 270 top
PC6386  4.7U_0603_6.3V6K  [C_0603]  196.98 61.87 270 top
PC6387  4.7U_0603_6.3V6K  [C_0603]  195.77 61.87 270 top
PC6388  470U_D2_2VM_R4.5M~D  [C_D1]  205.66 65.63 180 bottom
PC6389  470U_D2_2VM_R4.5M~D  [C_D1]  196.62 65.62 180 bottom
PC6390  470U_D2_2VM_R4.5M~D  [C_D1]  188.94 101.5 0 top
PC6391  470U_D2_2VM_R4.5M~D  [C_D1]  196.22 93.43 0 top
PC6392  10U_0603_6.3V6M  [C_0603]  174.83 118.83 90 bottom
PC6393  10U_0603_6.3V6M  [C_0603]  189.61 60.8 180 bottom
PC6394  10U_0603_6.3V6M  [C_0603]  189.61 59.58 180 bottom
PC6395  10U_0603_6.3V6M  [C_0603]  189.61 62.05 180 bottom
PC6396  10U_0603_6.3V6M  [C_0603]  189.63 58.06 0 top
PC6397  10U_0603_6.3V6M  [C_0603]  210.14 61.87 270 top
PC6398  10U_0603_6.3V6M  [C_0603]  208.93 61.87 270 top
PC6399  10U_0603_6.3V6M  [C_0603]  211.34 61.87 270 top
PC6400  10U_0603_6.3V6M  [C_0603]  189.63 59.27 0 top
PC6401  10U_0603_6.3V6M  [C_0603]  189.63 55.84 180 bottom
PC6402  10U_0603_6.3V6M  [C_0603]  189.63 57.11 180 bottom
PC6403  10U_0603_6.3V6M  [C_0603]  189.69 60.54 0 top
PC6404  10U_0603_6.3V6M  [C_0603]  189.63 56.86 0 top
PC6405  10U_0603_6.3V6M  [C_0603]  177.43 118.83 90 bottom
PC6406  10U_0603_6.3V6M  [C_0603]  178.77 118.83 90 bottom
PC6407  10U_0603_6.3V6M  [C_0603]  176.1 118.83 90 bottom
PC6408  10U_0603_6.3V6M  [C_0603]  189.63 58.32 180 bottom
PC6409  10U_0603_6.3V6M  [C_0603]  196.29 98.2 270 top
PC6410  10U_0603_6.3V6M  [C_0603]  200.61 98.2 270 top
PC6411  10U_0603_6.3V6M  [C_0603]  202.13 98.2 270 top
PC6412  10U_0603_6.3V6M  [C_0603]  197.69 98.2 270 top
PC6413  10U_0603_6.3V6M  [C_0603]  192.99 98.2 270 top
PC6414  10U_0603_6.3V6M  [C_0603]  190.07 98.2 270 top
PC6415  470U_D2_2VM_R4.5M~D  [C_D1]  220.87 61.5 270 top
PC8200  2.2U_0603_16V6K  [C_0603]  248.93 63.84 90 top
PC8201  2200P_0402_50V7K  [C_0402]  244.57 54.7 180 top
PC8202  0.1U_0402_25V6  [C_0402]  244.57 54.7 180 bottom
PC8203  10U_0805_25V6K~D  [C_0805]  244.96 58.63 180 bottom
PC8204  10U_0805_25V6K~D  [C_0805]  244.96 56.92 180 bottom
PC8205  0.1U_0402_25V6  [C_0402]  257.94 63.76 180 top
PC8206  0.22U_0603_25V7K  [C_0603]  249.89 60.34 270 top
PC8207  220U_D2 SX_2VY_R9M  [C_D2]  224.78 65.45 270 bottom
PC8208  220U_D2 SX_2VY_R9M  [C_D2]  229.47 65.48 270 bottom
PC8209  680P_0402_50V7K  [C_0402]  235.15 59.59 0 top
PC8211  0.1U_0402_25V6  [C_0402]  255.02 58.05 0 top
PC8212  0.22U_0603_25V7K  [C_0603]  250.14 64.1 90 top
PC8213  10U_0805_25V6K~D  [C_0805]  244.96 56.92 180 top
PC8214  10U_0805_25V6K~D  [C_0805]  244.96 58.63 180 top
PC8215  0.1U_0402_25V6  [C_0402]  258.01 61.81 0 top
PC8216  2200P_0402_50V7K  [C_0402]  258 60.92 0 top
PC8217  47P_0402_50V8J  [C_0402]  259.09 63.96 90 top
PC8218  0.1U_0402_25V6  [C_0402]  257.05 64.79 0 top
PC8219  680P_0402_50V7K  [C_0402]  245.65 74.95 180 top
PC8220  1U_0402_25V6K  [C_0402]  244.57 55.59 180 top
PC8221  1000P_0402_50V7K  [C_0402]  244.57 55.59 180 bottom
PC8222  0.1U_0402_25V6  [C_0402]  260.61 58.38 0 top
PD1  SM24_SOT23  [TP0610K-T1-E3_SOT23-3]  277.26 38.28 0 top
PD2  -  [TVNST52302AB0_SOT523-3]  59.23 4.53 180 top
PD3  -  [TVNST52302AB0_SOT523-3]  57.15 4.52 180 top
PD5  -  [BAS40CW_SOT323-3]  258.01 54.98 0 top
PD100  -  [BAS40CW_SOT323-3]  34.55 19.89 0 top
PD101  -  [LL4148_LL34-2]  33.79 18.3 0 bottom
PD700  BAT54CW-7-F SOT-323  [BAT54CW_SOT323-3]  61.93 30 90 top
PH1  100K_0402_1%_B25/50 4250K  [R_0402]  123.77 101.92 270 top
PH500  470K_0402_5%_B25/50 4700K  [R_0402]  109.58 136.49 270 bottom
PH501  10K +-5% 0402 B25/50 4250K  [R_0402]  159.31 119.22 180 bottom
PH502  10K +-5% 0402 B25/50 4250K  [R_0402]  120.73 120.48 0 bottom
PH503  10K +-5% 0402 B25/50 4250K  [R_0402]  135.89 120.44 0 bottom
PH504  470K_0402_5%_B25/50 4700K  [R_0402]  134.75 137.46 0 bottom
PJ800  -  [JUMP_43X39]  163.21 147.2 90 bottom
PJP100  -  [JUMP_43X118]  42.36 16.95 270 top
PJP101  -  [JUMP_43X118]  37.09 16.95 270 top
PJP102  -  [JUMP_43X118]  40.18 37.67 180 bottom
PJP103  -  [JUMP_43X39]  49.75 28.75 180 top
PJP104  -  [JUMP_43X118]  40.18 32.44 180 bottom
PJP200  -  [JUMP_43X118]  70.62 34.09 270 bottom
PJP201  -  [JUMP_43X118]  65.41 34.09 270 bottom
PJP202  -  [JUMP_43X39]  67.76 53.43 0 top
PJP203  -  [JUMP_43X39]  63.63 45.76 0 top
PJP300  -  [JUMP_43X118]  184.52 14.44 180 bottom
PJP301  -  [JUMP_43X39]  205.83 16.55 180 top
PJP302  -  [JUMP_43X118]  184.52 19.67 180 bottom
PJP504  -  [JUMP_43X39]  88.56 111.81 270 bottom
PJP505  -  [JUMP_43X118]  87.96 93.79 270 top
PJP700  -  [JUMP_43X39]  53.47 29.25 0 top
PJP801  -  [JUMP_43X79]  176.1 151.51 270 bottom
PJP802  -  [JUMP_43X39]  241.22 145.9 90 bottom
PJP803  -  [JUMP_43X79]  236.17 146.31 270 bottom
PJP1300  -  [JUMP_43X79]  159.7 22.95 180 bottom
PJP1301  -  [JUMP_43X79]  166.36 16 90 bottom
PJP8200  -  [JUMP_43X39]  244.13 53.47 270 top
PJP8201  -  [JUMP_43X118]  223.92 68.82 90 bottom
PJP8202  -  [JUMP_43X118]  229.19 68.82 90 bottom
PJPDC1  ACES_51202-00901-001  [ACES_51202-00901-001_9P-T]  25.66 51.44 0 bottom
PL1  SMB3025500YA_2P  [CHENG_SMB3025500YA_2P]  36.64 45.93 0 bottom
PL2  BLM15HG601SN1D_2P  [MURAT_BLM15HG601SN1D_2P]  23.88 46.06 90 bottom
PL3  SMB3025500YA_2P  [CHENG_SMB3025500YA_2P]  36.64 42.31 0 bottom
PL4  SMB3025500YA_2P  [CHENG_SMB3025500YA_2P]  68.87 19.51 180 bottom
PL5  SMB3025500YA_2P  [CHENG_SMB3025500YA_2P]  68.87 23 180 bottom
PL101  S COIL 1.5UH +-20% 9A 7X7X3  [L_7X7X3_M_2P]  43.63 33.29 0 bottom
PL102  S COIL 1.5UH +-20% 9A 7X7X3  [L_7X7X3_M_2P]  46.29 25.71 180 bottom
PL201  1UH_11A_20%_7X7X3_M  [L_7X7X3_M_2P]  68.46 47.07 90 bottom
PL300  1UH_11A_20%_7X7X3_M  [L_7X7X3_M_2P]  199.14 15.83 90 bottom
PL500  FBMA-L11-453215800LMA90T_2P  [KC_FBMA-L11-453215800LMA90T_2P]  96.26 117.75 0 bottom
PL501  0.15UH_PCME064T-R15MS0R667_36A_20%  [CYNTE_PCME064T-R15MS0R667_2P]  132.54 122.02 90 bottom
PL502  0.15UH_PCME064T-R15MS0R667_36A_20%  [CYNTE_PCME064T-R15MS0R667_2P]  140.22 121.96 90 bottom
PL503  0.15UH_PCME064T-R15MS0R667_36A_20%  [CYNTE_PCME064T-R15MS0R667_2P]  147.9 122.02 90 bottom
PL505  0.15UH_PCME064T-R15MS0R667_36A_20%  [CYNTE_PCME064T-R15MS0R667_2P]  117.3 122.02 90 bottom
PL506  0.15UH_PCME064T-R15MS0R667_36A_20%  [CYNTE_PCME064T-R15MS0R667_2P]  124.92 122.02 90 bottom
PL508  0.47UH_PCMB053T-R47MS_12A_20%  [CYNTE_PCMB053T-R47MS_2P]  154.93 122.04 270 bottom
PL509  1UH_PCMB042T-1R0MS_4.5A_20%  [CYNTE_PCMB042T-1R0MS_2P]  90.82 100.39 270 bottom
PL700  2.2UH_PCMB104T-2R2MS_12A_20%  [CYNTE_PCMB104T-2R2MS_2P]  50.8 23.38 0 bottom
PL800  1UH_PCMB042T-1R0MS_4.5A_20%  [CYNTE_PCMB042T-1R0MS_2P]  168.09 152.61 0 bottom
PL801  1UH_1239AS-H-1R0M-P2_3A_20%  [TOKO_1239AS-H-1R0M-P2_2P]  236.98 151.28 180 bottom
PL6100  0.22UH_MMD-10DZIR22M-R1L__50A_20%  [L_10X10X4_M]  206.33 51.32 90 bottom
PL6101  0.22UH_MMD-10DZIR22M-R1L__50A_20%  [L_10X10X4_M]  195.53 51.3 90 bottom
PL6200  0.22UH_MMD-10DZIR22M-R1L__50A_20%  [L_10X10X4_M]  217.08 51.32 90 bottom
PL8200  1UH_11A_20%_7X7X3_M  [L_7X7X3_M_2P]  239.78 61.37 180 bottom
PL8201  1UH_11A_20%_7X7X3_M  [L_7X7X3_M_2P]  239.76 68.93 180 bottom
PQ2  S TR METR3904W-G NPN SOT323-3  [RHU002N06_SOT323-3]  282.68 37.79 90 top
PQ3  -  [SI3457CDV-T1-GE3_TSOP6]  47.37 8.18 0 top
PQ4  L2N7002WT1G 1N SC-70-3  [SSM3K7002FU_SC70-3]  50.56 6.82 180 top
PQ7  FDV301N_G 1N SOT23-3  [FDV301N_NL_SOT23-3]  281.75 41.11 270 top
PQ8  L2N7002WT1G 1N SC-70-3  [SSM3K7002FU_SC70-3]  54.94 4.73 0 top
PQ100  -  [AON7518_DFN8-5]  49.22 36.84 180 top
PQ101  -  [AON7534_DFN3X3-8-5]  43.54 33.96 0 top
PQ102  -  [AON7518_DFN8-5]  44.61 23.83 0 top
PQ103  -  [AON7534_DFN3X3-8-5]  42.61 27 180 top
PQ200  -  [AON7408L_DFN8-5]  68.71 51.39 180 top
PQ201  -  [AON7506_DFN33-8-5]  70.43 48.27 0 top
PQ202  S TR 2N7002KDW 2N SOT-363-6  [2N7002DW-7-F_SOT363-6]  56.78 48.28 180 top
PQ300  -  [AON7408L_DFN8-5]  203.87 17.09 90 bottom
PQ301  -  [AON7506_DFN33-8-5]  206.74 22.62 270 bottom
PQ700  L2N7002WT1G 1N SC-70-3  [SSM3K7002FU_SC70-3]  49.22 42.12 270 top
PQ701  -  [MDU1512RH_POWERDFN56-8-5]  49.41 48.4 270 bottom
PQ702  -  [MDU1512RH_POWERDFN56-8-5]  52.52 44.72 90 bottom
PQ703  -  [AON7506_DFN33-8-5]  63.5 24.34 0 top
PQ704  -  [AON6414AL_DFN8-5]  56.52 18.94 0 top
PQ705  L2N7002WT1G 1N SC-70-3  [SSM3K7002FU_SC70-3]  52.84 31.64 270 top
PQ706  -  [AON7518_DFN8-5]  54.36 24.14 180 top
PQ707  -  [MDU1512RH_POWERDFN56-8-5]  49.41 44.59 90 top
PQ710  S TR 2N7002KDW 2N SOT-363-6  [2N7002DW-7-F_SOT363-6]  90.21 71.96 270 top
PQ6100  AON6992_DFN5X6D-8-7  [AON6970_DFN5X6D-8-7]  209.11 41.67 270 bottom
PQ6101  AON6992_DFN5X6D-8-7  [AON6970_DFN5X6D-8-7]  209.15 47.39 270 bottom
PQ6102  AON6992_DFN5X6D-8-7  [AON6970_DFN5X6D-8-7]  192.91 38.17 90 bottom
PQ6103  AON6992_DFN5X6D-8-7  [AON6970_DFN5X6D-8-7]  192.93 43.82 90 bottom
PQ6200  AON6992_DFN5X6D-8-7  [AON6970_DFN5X6D-8-7]  218.87 47.64 270 bottom
PQ6201  AON6992_DFN5X6D-8-7  [AON6970_DFN5X6D-8-7]  218.85 42.12 270 bottom
PQ8200  AON6992 2N DFN5X6D  [AON6970_DFN5X6D-8-7]  243.51 60.67 90 top
PQ8201  AON6992 2N DFN5X6D  [AON6970_DFN5X6D-8-7]  245.72 67.78 90 top
PQ8202  DMN53D0LDW-7 2N SOT363-6  [2N7002DW-7-F_SOT363-6]  260.4 60.88 270 top
PR2  1K_0402_1%  [R_0402]  256.36 56.3 270 top
PR3  2.2K_0402_5%  [R_0402]  285.6 40.73 270 top
PR4  33_0402_5%  [R_0402]  285.6 42.57 270 top
PR6  100K_0402_1%  [R_0402]  279.96 39.85 90 top
PR8  10K_0402_1%  [R_0402]  283.96 37.56 90 top
PR9  15K_0402_1%  [R_0402]  279.96 38.07 90 top
PR12  100K_0402_1%  [R_0402]  51.88 10.18 270 top
PR13  100K_0402_1%  [R_0402]  51.88 7.15 90 top
PR14  100K_0402_1%  [R_0402]  46.91 5.58 270 top
PR16  10K_0402_1%  [R_0402]  56.78 7 90 top
PR17  0_0402_5%  [R0402_0OHM]  47.78 6.52 180 top
PR19  100_0402_1%  [R_0402]  59.69 7.89 270 top
PR21  100_0402_1%  [R_0402]  58.74 7.89 270 top
PR22  100_0402_1%  [R_0402]  57.79 7.89 270 top
PR23  110K_0402_1%  [R_0402]  82.3 15.69 180 top
PR24  14.7K_0402_1%  [R_0402]  286.59 36.89 90 top
PR25  12.1K_0402_1%  [R_0402]  285.51 36.89 90 top
PR26  100K_0402_1%  [R_0402]  82.28 13.9 90 top
PR28  100K_0402_1%  [R_0402]  54.61 7.9 0 top
PR100  0_0402_5%  [R0402_0OHM]  37.1 22.66 270 top
PR101  6.49K_0402_1%  [R_0402]  30.23 28.68 0 bottom
PR102  15.8K_0402_1%  [R_0402]  31.33 25.51 180 bottom
PR103  10K_0402_1%  [R_0402]  30.23 27.67 0 bottom
PR104  10K_0402_1%  [R_0402]  31.83 24.44 270 bottom
PR105  69.8K_0402_1%  [R_0402]  32.52 31.36 270 bottom
PR106  68.1K_0402_1%  [R_0402]  32.71 23.53 90 bottom
PR107  200_0402_1%  [R_0402]  33.6 24.44 270 bottom
PR108  0_0603_5%  [R_0603]  35.82 32.27 270 bottom
PR109  0_0603_5%  [R_0603]  35.56 24.02 270 bottom
PR110  4.7_1206_5%  [R_1206]  41.57 36.4 270 top
PR111  4.7_1206_5%  [R_1206]  41.1 22.33 270 top
PR112  0_0402_5%  [R0402_0OHM]  36.21 22.66 270 top
PR113  2.2K_0402_5%  [R_0402]  36.21 19.97 90 top
PR114  0_0402_5%  [R0402_0OHM]  37.1 19.97 90 top
PR115  1M_0402_1%  [R_0402]  35.25 19.91 90 bottom
PR116  200K_0402_1%  [R_0402]  36.14 20.82 270 bottom
PR200  2.2_0603_5%  [R_0603]  64.96 48.72 90 top
PR201  20.5K_0402_1%  [R_0402]  61.61 46.7 90 top
PR202  4.7_1206_5%  [R_1206]  74.17 50.81 270 top
PR203  5.1_0603_5%  [R_0603]  61.54 46.22 90 bottom
PR204  2.2_0603_5%  [R_0603]  60.33 46.24 90 top
PR205  12K_0402_1%  [R_0402]  58.08 52.28 90 bottom
PR206  887K_0402_1%  [R_0402]  57.21 50.12 0 top
PR207  20K_0402_1%  [R_0402]  59.49 52.34 0 bottom
PR208  0_0402_5%  [R0402_0OHM]  58.12 51.07 180 top
PR209  0_0402_5%  [R_0402]  57.21 52.97 0 top
PR210  100K_0402_1%  [R_0402]  59.25 46.94 90 top
PR211  0_0402_5%  [R0402_0OHM]  58.12 52.02 180 top
PR212  1K_0402_1%  [R_0402]  54.23 45.17 0 top
PR213  60.4K_0402_1%  [R_0402]  54.5 48.49 270 top
PR214  1K_0402_1%  [R_0402]  52.53 49.06 270 top
PR215  60.4K_0402_1%  [R_0402]  55.83 50.14 270 top
PR300  0_0402_5%  [R0402_0OHM]  216.71 20.06 180 top
PR301  100K_0402_1%  [R_0402]  213.83 17.47 0 top
PR302  2.2_0603_5%  [R_0603]  210.65 17.34 180 top
PR303  200K_0402_1%  [R_0402]  216.7 19.12 180 top
PR305  4.7_1206_5%  [R_1206]  204.8 24.36 0 bottom
PR306  470K_0402_1%  [R_0402]  214.26 22.7 90 top
PR307  4.42K_0402_1%  [R_0402]  215.79 22.86 0 top
PR308  10K_0402_1%  [R_0402]  215.79 21.97 0 top
PR500  95.3K_0402_1%  [R_0402]  91.09 129.75 180 top
PR501  45.3_0402_1%  [R_0402]  91.99 125.01 90 top
PR502  75_0402_1%  [R_0402]  92.88 125.01 90 top
PR503  100_0402_1%  [R_0402]  93.77 125.01 90 top
PR504  0_0402_5%  [R0402_0OHM]  91.11 127.42 90 bottom
PR505  1_0402_5%  [R_0402]  93.78 127.42 90 top
PR506  0_0402_5%  [R0402_0OHM]  95.57 128.33 180 top
PR507  0_0402_5%  [R0402_0OHM]  92 125.93 270 bottom
PR508  49.9_0402_1%  [R_0402]  92 127.42 90 bottom
PR509  0_0402_5%  [R0402_0OHM]  92.89 125.93 270 bottom
PR510  0_0402_5%  [R0402_0OHM]  92.89 127.42 90 bottom
PR511  0_0402_5%  [R0402_0OHM]  93.78 125.93 270 bottom
PR512  10_0402_1%  [R_0402]  93.78 127.42 90 bottom
PR513  27.4K_0402_1%  [R_0402]  86.59 127.37 0 bottom
PR514  12.4K_0402_1%  [R_0402]  87.48 128.26 0 bottom
PR515  1.91K_0402_1%  [R_0402]  89.22 127.85 0 top
PR516  16.9K_0402_1%  [R_0402]  96.44 128.34 270 bottom
PR517  28K_0402_1%  [R_0402]  95.56 128.34 270 bottom
PR518  110K_0402_1%  [R_0402]  94.67 128.34 270 bottom
PR519  169K_0402_1%  [R_0402]  97.33 128.34 270 bottom
PR520  0_0402_5%  [R0402_0OHM]  90.13 128.8 180 top
PR521  3.6K_0402_1%  [R_0402]  88.85 132.24 270 top
PR522  2K_0402_1%  [R_0402]  86.6 131.32 270 bottom
PR523  0_0402_5%  [R0402_0OHM]  90.22 128.34 270 bottom
PR524  1.27K_0402_1%  [R_0402]  99.23 131.5 0 bottom
PR525  1K_0402_1%  [R_0402]  87.49 130.41 90 bottom
PR526  0_0402_5%  [R0402_0OHM]  89.33 127.42 90 bottom
PR527  48.7K_0402_1%  [R_0402]  95.77 129.68 90 top
PR528  1K_0402_1%  [R_0402]  100.15 130.61 270 bottom
PR529  11K_0402_1%  [R_0402]  100.14 134.15 180 bottom
PR530  3.6K_0402_1%  [R_0402]  158.39 120.11 0 bottom
PR531  2.94K_0402_1%  [R_0402]  88.38 131.32 270 bottom
PR532  316_0402_1%  [R_0402]  99.22 135.98 0 bottom
PR533  2.74K_0402_1%  [R_0402]  99.23 135.06 0 bottom
PR534  2.61K_0402_1%  [R_0402]  90.63 139.95 180 top
PR535  11K_0402_1%  [R_0402]  88.39 132.2 180 bottom
PR536  2K_0402_1%  [R_0402]  99.23 136.9 0 bottom
PR537  4.53K_0402_1%  [R_0402]  96.72 134.4 270 top
PR538  1K_0402_1%  [R_0402]  87.54 136.65 0 bottom
PR539  113K_0402_1%  [R_0402]  96.42 135.87 180 top
PR540  301_0402_1%  [R_0402]  87.55 135.77 270 bottom
PR541  392_0402_1%  [R_0402]  94.34 138.17 0 bottom
PR542  11K_0402_1%  [R_0402]  91.43 139.07 270 top
PR543  1K_0402_1%  [R_0402]  96.13 139.07 270 bottom
PR544  4.42K_0402_1%  [R_0402]  90.54 139.07 270 top
PR545  12.4K_0402_1%  [R_0402]  90.46 138.17 0 bottom
PR546  1K_0402_1%  [R_0402]  92.32 138.16 90 bottom
PR547  27.4K_0402_1%  [R_0402]  89.59 139.07 270 bottom
PR548  93.1K_0402_1%  [R_0402]  90.02 135.42 270 top
PR549  2K_0402_1%  [R_0402]  91.43 139.05 90 bottom
PR550  3.57K_0402_1%  [R_0402]  93.21 139.07 270 bottom
PR551  4.87K_0402_1%  [R_0402]  91.89 136.74 0 top
PR552  0_0402_5%  [R0402_0OHM]  129.28 138 270 bottom
PR553  1_0402_5%  [R_0402]  131.06 137.08 90 bottom
PR554  4.7_0603_1%  [R_0603]  133.37 138.39 270 bottom
PR555  10_1206_5%  [R_1206]  130.25 128.57 0 top
PR556  0_0402_5%  [R0402_0OHM]  130.17 138 270 bottom
PR557  3.65K_0603_1%  [R_0603]  131.05 126.93 0 top
PR558  100K_0402_1%  [R_0402]  132.47 125.73 180 top
PR559  10_0402_1%  [R_0402]  132.51 123.92 90 top
PR560  100K_0402_1%  [R_0402]  131.58 123.91 90 top
PR561  100K_0402_1%  [R_0402]  130.67 123.92 90 top
PR562  20M_0402_5%  [R_0402]  130.06 127.12 270 top
PR563  0_0402_5%  [R0402_0OHM]  137.81 137.9 270 bottom
PR564  4.7_0603_1%  [R_0603]  141.89 138.32 270 bottom
PR565  10_1206_5%  [R_1206]  139.08 128.5 0 top
PR566  0_0402_5%  [R0402_0OHM]  138.7 137.9 270 bottom
PR567  3.65K_0603_1%  [R_0603]  138.95 126.92 0 top
PR568  100K_0402_1%  [R_0402]  139.87 125.86 180 top
PR569  10_0402_1%  [R_0402]  139.9 124.05 90 top
PR570  100K_0402_1%  [R_0402]  138.06 124.05 90 top
PR571  100K_0402_1%  [R_0402]  138.95 124.05 90 top
PR572  20M_0402_5%  [R_0402]  113.61 127.5 270 top
PR573  0_0402_5%  [R0402_0OHM]  145.74 137.98 270 bottom
PR574  4.7_0603_1%  [R_0603]  149.85 138.37 270 bottom
PR575  10_1206_5%  [R_1206]  146.95 128.57 0 top
PR576  0_0402_5%  [R0402_0OHM]  146.66 137.97 270 bottom
PR577  3.65K_0603_1%  [R_0603]  146.77 126.91 0 top
PR578  100K_0402_1%  [R_0402]  147.6 125.77 180 top
PR579  10_0402_1%  [R_0402]  147.59 123.92 90 top
PR580  100K_0402_1%  [R_0402]  146.63 123.92 90 top
PR581  100K_0402_1%  [R_0402]  145.74 123.92 90 top
PR582  20M_0402_5%  [R_0402]  159.78 122.5 90 top
PR583  4.7_0603_1%  [R_0603]  116.91 138.33 270 bottom
PR584  4.7_1206_5%  [R_1206]  114.76 128.38 0 top
PR585  0_0402_5%  [R0402_0OHM]  113.71 137.93 270 bottom
PR586  3.65K_0603_1%  [R_0603]  114.66 126.74 0 top
PR587  100K_0402_1%  [R_0402]  116.65 125.69 180 top
PR588  10_0402_1%  [R_0402]  116.65 123.9 90 top
PR589  100K_0402_1%  [R_0402]  115.68 123.89 90 top
PR590  0_0402_5%  [R0402_0OHM]  112.82 137.93 270 bottom
PR591  0_0402_5%  [R0402_0OHM]  121.15 138.02 270 bottom
PR592  4.7_0603_1%  [R_0603]  125.24 138.42 270 bottom
PR593  4.7_1206_5%  [R_1206]  122.44 128.5 0 top
PR594  0_0402_5%  [R0402_0OHM]  122.04 138.02 270 bottom
PR595  3.65K_0603_1%  [R_0603]  122.72 126.83 0 top
PR596  100K_0402_1%  [R_0402]  124.1 125.77 180 top
PR597  10_0402_1%  [R_0402]  124.13 124.01 90 top
PR598  100K_0402_1%  [R_0402]  123.17 124.01 90 top
PR599  10K_0402_1%  [R_0402]  129.03 134.82 270 top
PR700  1M_0402_1%  [R_0402]  49.21 42.38 0 bottom
PR701  3M_0402_5%  [R_0402]  51.06 42.29 90 bottom
PR702  0.005_1206_1%  [R_1206_4P-D]  56.52 42.56 0 bottom
PR703  0_0402_5%  [R0402_0OHM]  57.67 41.06 270 bottom
PR704  0_0402_5%  [R0402_0OHM]  58.56 41.06 270 bottom
PR705  4.12K_0603_1%  [R_0603]  63.69 34.75 180 top
PR706  4.12K_0603_1%  [R_0603]  63.69 33.48 180 top
PR707  10_1206_1%  [R_1206]  61.67 28.36 90 bottom
PR708  2.2_0603_5%  [R_0603]  57.86 29.57 90 top
PR709  20K_0402_1%  [R_0402]  54.87 32.15 270 bottom
PR710  6.49K_0402_1%  [R_0402]  53.92 31.19 90 bottom
PR711  1.62K_0402_1%  [R_0402]  56.45 34.57 0 bottom
PR712  0.01_1206_1%  [R_1206_4P-D]  65.19 25.86 0 bottom
PR713  4.7_1206_5%  [R_1206]  50.36 19.95 90 top
PR714  100K_0402_1%  [R_0402]  63.12 35.94 180 top
PR715  120K_0402_5%  [R_0402]  62.24 35.09 270 bottom
PR716  324K_0402_1%  [R_0402]  63.12 36.84 180 top
PR717  0_0402_5%  [R0402_0OHM]  63.12 37.9 90 top
PR718  10K_0402_1%  [R_0402]  54.61 36.08 180 bottom
PR719  49.9K_0402_1%  [R_0402]  62.22 36.84 0 bottom
PR720  0_0402_5%  [R0402_0OHM]  57.04 39.45 180 top
PR721  0_0402_5%  [R0402_0OHM]  57.04 38.5 180 top
PR722  10_0402_1%  [R_0402]  54.63 33.35 180 top
PR723  10_0402_1%  [R_0402]  54.63 34.24 180 top
PR724  0_0402_5%  [R_0402]  59.06 39.45 270 top
PR725  4.7_0402_5%  [R_0402]  47.33 42.89 180 bottom
PR726  4.7_0402_5%  [R_0402]  48.07 49.99 0 top
PR727  0_0402_5%  [R0402_0OHM]  54.64 37.43 180 top
PR728  0_0402_5%  [R_0402]  58.75 36.02 90 bottom
PR729  1M_0402_1%  [R_0402]  93.11 72.17 270 top
PR730  1M_0402_1%  [R_0402]  91.27 73.11 0 top
PR731  200K_0402_1%  [R_0402]  88.22 70.32 90 top
PR732  3.3K_0402_1%  [R_0402]  89.11 70.32 90 top
PR733  10K_0402_1%  [R_0402]  53.71 35.13 0 top
PR734  10_0402_1%  [R_0402]  53.72 36.03 0 top
PR801  30K_0402_1%  [R_0402]  160.62 157.63 180 bottom
PR802  1M_0402_1%  [R_0402]  162.71 158.01 180 bottom
PR803  4.7_0603_5%  [R_0603]  163.34 151.09 270 top
PR804  21.5K_0402_1%  [R_0402]  164.54 158.41 270 bottom
PR805  31.6K_0402_1%  [R_0402]  165.51 156.23 180 bottom
PR806  0_0603_5%  [R_0603]  165.3 150.09 270 bottom
PR807  0_0402_5%  [R0402_0OHM]  237.95 154.06 90 bottom
PR808  1M_0402_1%  [R_0402]  239.85 154.06 90 bottom
PR809  4.7_0603_5%  [R_0603]  237.38 149.45 0 bottom
PR810  22.1K_0402_1%  [R_0402]  241.79 154.05 90 bottom
PR811  10.7K_0402_1%  [R_0402]  240.87 154.06 90 bottom
PR812  0_0402_5%  [R_0402]  163.59 157.49 90 bottom
PR813  0_0402_5%  [R0402_0OHM]  163.73 156.23 180 bottom
PR820  10K_0402_5%  [R_0402]  236.22 152.93 0 bottom
PR821  10K_0402_5%  [R_0402]  161.76 154.01 180 bottom
PR823  0_0402_5%  [R_0402]  159.7 156.68 0 bottom
PR1300  100K_0402_1%  [R_0402]  167.82 18.64 90 bottom
PR1301  0_0402_5%  [R0402_0OHM]  166.74 19.56 270 bottom
PR1302  1M_0402_1%  [R_0402]  165.79 19.56 270 bottom
PR1304  21.5K_0402_1%  [R_0402]  165.8 28.74 0 bottom
PR1305  10K_0402_1%  [R_0402]  165.8 27.88 0 bottom
PR5001  0_0402_5%  [R0402_0OHM]  152.86 130.78 90 bottom
PR5002  4.7_1206_5%  [R_1206]  156.03 122.86 180 top
PR5003  3.65K_0603_1%  [R_0603]  157.43 123.21 0 top
PR5004  1_0402_5%  [R_0402]  139.59 136.98 90 bottom
PR5005  1_0603_5%  [R_0603]  156.86 130.73 0 bottom
PR5006  0_0402_5%  [R0402_0OHM]  153.75 131.69 270 bottom
PR5007  0_0402_5%  [R0402_0OHM]  95.91 109.5 180 bottom
PR5008  1M_0402_1%  [R_0402]  95 108.61 0 bottom
PR5009  4.7_1206_5%  [R_1206]  94.12 101.56 270 bottom
PR5010  0_0603_5%  [R_0603]  88.79 104.82 270 bottom
PR5011  10K_0402_1%  [R_0402]  137.55 134.83 270 top
PR5012  21K_0402_1%  [R_0402]  91.61 111.56 90 bottom
PR5014  10_0402_1%  [R_0402]  92.52 112.47 270 bottom
PR5015  35.7K_0402_1%  [R_0402]  90.73 112.45 270 bottom
PR5016  10K_0402_5%  [R_0402]  94.13 109.69 180 bottom
PR5017  0_0402_5%  [R0402_0OHM]  93.73 111.61 0 bottom
PR5018  0_0402_5%  [R0402_0OHM]  93.73 112.5 0 bottom
PR5019  10K_0402_1%  [R_0402]  145.8 134.87 270 top
PR5020  1_0402_5%  [R_0402]  147.54 137.06 90 bottom
PR5021  10K_0402_1%  [R_0402]  112.57 134.82 270 top
PR5022  1_0402_5%  [R_0402]  114.6 137.02 90 bottom
PR5023  10K_0402_1%  [R_0402]  120.9 134.91 270 top
PR5024  1_0402_5%  [R_0402]  122.93 137.11 90 bottom
PR5025  1_0402_5%  [R_0402]  154.63 130.78 90 bottom
PR5026  1_0402_5%  [R_0402]  152.86 129.34 270 top
PR5027  10_0402_1%  [R_0402]  159.31 118.33 180 bottom
PR5028  1_0402_5%  [R_0402]  129.9 133.03 180 top
PR5029  1_0402_5%  [R_0402]  138.41 133.03 180 top
PR5030  1_0402_5%  [R_0402]  146.36 133.09 180 top
PR5031  1_0402_5%  [R_0402]  113.46 133.03 180 top
PR5032  1_0402_5%  [R_0402]  121.79 133.15 180 top
PR5033  0_0402_5%  [R_0402]  95.91 105.88 180 bottom
PR5034  0_0402_5%  [R0402_0OHM]  95.91 106.83 180 bottom
PR6100  0.005_2512_1%  [RL-3264-9W-R005-FNH_2512_2512]  245.51 44.56 180 top
PR6101  0.005_2512_1%  [RL-3264-9W-R005-FNH_2512_2512]  241.17 51.87 270 top
PR6102  1M_0402_1%  [R_0402]  203.77 30.19 0 top
PR6103  30K_0402_5%  [R_0402]  205.7 32.35 180 bottom
PR6104  2.2_0603_1%  [R_0603]  203.45 32.31 90 bottom
PR6105  2.2_0603_1%  [R_0603]  196.67 32.22 90 bottom
PR6107  10K_0402_5%  [R_0402]  196.38 31.28 180 bottom
PR6108  0_0402_5%  [R0402_0OHM]  204.68 30.18 180 bottom
PR6109  75K_0402_1%  [R_0402]  198.52 30.56 90 top
PR6110  0_0402_5%  [R0402_0OHM]  203.79 28.33 90 bottom
PR6112  82.5K_0402_1%  [R_0402]  195.44 30.38 0 bottom
PR6113  49.9_0402_1%  [R_0402]  195.28 29.98 90 top
PR6115  10K_0402_5%  [R_0402]  195.44 29.5 0 bottom
PR6117  71.5K_0402_1%  [R_0402]  199.36 27.64 270 bottom
PR6118  4.32K_0402_1%  [R_0402]  201.1 27.64 270 bottom
PR6119  6.19K_0402_1%  [R_0402]  202.02 27.64 270 bottom
PR6120  16.5K_0402_1%  [R_0402]  199.42 26.88 180 top
PR6122  0_0402_5%  [R0402_0OHM]  198.47 26.73 90 bottom
PR6123  0_0402_5%  [R0402_0OHM]  196.59 26.73 90 bottom
PR6125  309_0402_1%  [R_0402]  197.56 27.85 270 top
PR6126  100_0402_5%  [R_0402]  174.89 114.34 270 bottom
PR6127  20.5K_0402_1%  [R_0402]  200.24 27.64 270 bottom
PR6128  100_0402_5%  [R_0402]  174.89 111.58 90 bottom
PR6129  2.2_0805_1%  [R_0805]  206.22 35.77 180 top
PR6130  2.2_0805_1%  [R_0805]  196.78 35.77 0 top
PR6132  5.1K_0402_1%  [R_0402]  205.63 28.33 90 bottom
PR6133  0_0402_5%  [R_0402]  204.74 28.33 90 bottom
PR6200  0.005_2512_1%  [RL-3264-9W-R005-FNH_2512_2512]  241.17 48 270 top
PR6201  30K_0402_5%  [R_0402]  218.4 31.9 180 bottom
PR6202  1M_0402_1%  [R_0402]  216.79 31.11 0 top
PR6203  2.2_0603_1%  [R_0603]  216.4 31.99 90 bottom
PR6205  10K_0402_5%  [R_0402]  209.56 31.99 180 bottom
PR6207  51.1K_0402_1%  [R_0402]  210.9 29.41 90 top
PR6208  0_0402_5%  [R0402_0OHM]  216.82 29.11 180 bottom
PR6210  82.5K_0402_1%  [R_0402]  208.65 31.08 0 bottom
PR6211  49.9_0402_1%  [R_0402]  207.98 30.36 90 top
PR6213  240K_0402_1%  [R_0402]  212.19 27.83 270 bottom
PR6214  10K_0402_5%  [R_0402]  208.65 30.2 0 bottom
PR6215  4.32K_0402_1%  [R_0402]  213.93 27.83 270 bottom
PR6216  6.19K_0402_1%  [R_0402]  214.84 27.83 270 bottom
PR6217  16.5K_0402_1%  [R_0402]  212.75 26.95 180 top
PR6219  0_0402_5%  [R0402_0OHM]  211.28 26.92 90 bottom
PR6220  0_0402_5%  [R0402_0OHM]  209.42 26.92 90 bottom
PR6222  309_0402_1%  [R_0402]  210.9 27.85 270 top
PR6223  100_0402_5%  [R_0402]  174.88 110.7 0 bottom
PR6224  20.5K_0402_1%  [R_0402]  213.07 27.83 270 bottom
PR6225  100_0402_5%  [R_0402]  174.88 109.18 0 bottom
PR6226  2.2_0805_1%  [R_0805]  215.06 34.95 0 top
PR6228  5.1K_0402_1%  [R_0402]  218.11 30.89 180 bottom
PR6229  0_0402_5%  [R_0402]  218.11 30 180 bottom
PR6230  5.1K_0402_1%  [R_0402]  217.4 28.07 270 bottom
PR8200  2.2_0603_5%  [R_0603]  250.08 62.51 180 top
PR8201  2.2_0402_1%  [R_0402]  258.91 62.69 0 top
PR8202  383K_0402_1%  [R_0402]  257.06 62.69 0 top
PR8203  4.7_1206_5%  [R_1206]  237.57 58.13 180 top
PR8204  100K_0402_1%  [R_0402]  254 65.68 0 top
PR8205  2.2_0603_1%  [R_0603]  251.17 58.95 0 top
PR8206  8.25K_0402_1%  [R_0402]  249.18 61.43 0 top
PR8207  2.2_0603_1%  [R_0603]  251.22 65.56 0 top
PR8208  10K_0402_1%  [R_0402]  257.11 61.78 270 top
PR8209  100_0402_5%  [R_0402]  256.76 65.68 180 top
PR8210  4.7_1206_5%  [R_1206]  242.71 73.49 0 top
PR8211  34.8K_0402_1%  [R_0402]  258 60.03 0 top
PR8214  0_0402_5%  [R0402_0OHM]  261.52 57.43 180 top
PR8215  52.3K_0402_1%  [R_0402]  258.92 59.08 180 top
